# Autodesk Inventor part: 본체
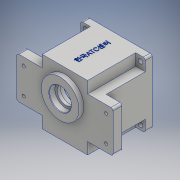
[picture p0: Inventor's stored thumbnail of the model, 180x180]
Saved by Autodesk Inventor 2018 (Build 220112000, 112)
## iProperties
Created: 2020-07
Part Number: 본체
Material: 알루미늄 6061
Document SubType Name: Modeling
Designer: Admin
Density: 2.7 g/cm^3
Appearance: 알루미늄 - 평지
Mass: 876.486 g
Surface Area: 793.573 cm^2
Volume: 324.624 cm^3
Author: Admin
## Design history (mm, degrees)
sketch "스케치1"
  geometry: L1 (47, 47)-(-47, 47); L2 (-47, 47)-(-47, -47); L3 (-47, -47)-(47, -47); L4 (47, -47)-(47, 47); L5 (47, 47)-(-47, -47); L6 (-47, 47)-(47, -47); 1 further point
  constraints: 12 end point, 2 midpoint, 2 parallel, 1 horizontal, 1 perpendicular
  dimensions: "d0" = 94 distance of L1.start L1.end; "d1" = 94 distance of L1.end L2.end
extrude "돌출1" new body sketch "스케치1" stored distance "d2" = 80; taper "d3" = 0 deg
sketch "스케치2"
  geometry: L1 (-65.8, 0)-(65.8, 0) reference; L2 (0, -65.8)-(0, 65.8) reference; L3 (-47, 47)-(-33, 47); L4 (-33, 47)-(-33, 30); L5 (-33, 30)-(-47, 30); L6 (-47, 30)-(-47, 47); L7 (33, 30)-(47, 30); L8 (33, 47)-(33, 30); L9 (47, 47)-(33, 47); L10 (47, 30)-(47, 47); L11 (-33, -30)-(-47, -30); L12 (-33, -47)-(-33, -30); L13 (-47, -47)-(-33, -47); L14 (-47, -30)-(-47, -47); L15 (33, -30)-(47, -30); L16 (33, -47)-(33, -30); L17 (47, -47)-(33, -47); L18 (47, -30)-(47, -47); 2 further points
  constraints: 32 end point, 12 symmetric about line, 2 parallel, 1 coincident, 1 horizontal, 1 perpendicular
  dimensions: "d4" = 33 distance between parallel lines of L2 L4; "d5" = 30 distance between parallel lines of L1 L5
extrude "돌출2" cut sketch "스케치2" distance "d6" = 70; taper "d7" = 0 deg
sketch "스케치3"
  geometry: L1 (-70, 30)-(70, 30); L2 (70, 30)-(70, -30); L3 (70, -30)-(-70, -30); L4 (-70, -30)-(-70, 30); L5 (0, -65.8)-(0, 65.8) reference; L6 (-92.406, 0)-(103.594, 0) reference; 1 further point
  constraints: 8 end point, 2 parallel, 1 horizontal, 1 perpendicular, 2 other
  dimensions: "d8" = 140 distance of L1.start L1.end; "d9" = 60 distance of L1.end L2.end
extrude "돌출3" join sketch "스케치3" distance "d10" = 13; taper "d11" = 0 deg
sketch "스케치4"
  geometry: L1 (-98, 0)-(98, 0) reference; L2 (0, -65.8)-(0, 65.8) reference; C1 r 27.5 at (0, 11); 1 further point
  constraints: 1 centre point, 1 point on line
  dimensions: "d12" = 55 diameter of C1; "d13" = 11 distance from line of L1 C1.centre
extrude "돌출4" join sketch "스케치4" distance "d14" = 7; taper "d15" = 0 deg
sketch "스케치5"
  geometry: C1 r 16 at (0, 0); C2 r 27.5 at (0, 0) reference; 1 further point
  constraints: 1 centre point, 1 concentric
  dimensions: "d16" = 32 diameter of C1
extrude "돌출5" cut sketch "스케치5" distance "d17" = 8.3; taper "d18" = 0 deg
sketch "스케치6"
  geometry: C1 r 12.5 at (0, 0); C2 r 16 at (0, 0) reference; 1 further point
  constraints: 1 centre point, 1 concentric
  dimensions: "d19" = 25 diameter of C1
extrude "돌출6" cut sketch "스케치6" extent not by distance; stored distance "d20" = 8.3; taper "d21" = 0 deg
sketch "스케치7"
  geometry: C1 r 43 at (0, 0); 1 further point
  constraints: 1 centre point, 1 coincident
  dimensions: "d22" = 86 diameter of C1
extrude "돌출7" cut sketch "스케치7" distance "d23" = 9; taper "d24" = 0 deg
sketch "스케치8"
  geometry: C1 r 40 at (0, 0); 1 further point
  constraints: 1 centre point, 1 coincident
  dimensions: "d25" = 80 diameter of C1
extrude "돌출8" cut sketch "스케치8" distance "d26" = 55; taper "d27" = 0 deg
sketch "스케치9"
  geometry: C1 r 17.5 at (0, -11); C2 r 12.5 at (0, -11) reference; 1 further point
  constraints: 1 centre point, 1 concentric
  dimensions: "d28" = 35 diameter of C1
extrude "돌출9" cut sketch "스케치9" distance "d29" = 10; taper "d30" = 0 deg
sketch "스케치10"
  geometry: C1 r 17.5 at (0, -11) reference; C2 r 40 at (0, 0); A1 r 21 centre (0, -11) between (-8.978, 7.984) and (8.978, 7.984); A2 r 15 centre (0, 20) between (8.978, 7.984) and (-8.978, 7.984); 1 further point
  constraints: 4 point on circle, 3 centre point, 1 coincident, 1 concentric, 1 vertical alignment
  dimensions: "d31" = 42 diameter of A1; "d32" = 30 diameter of A2; "d33" = 31 distance of A2.centre A1.centre; "d34" = 80 diameter of C2
extrude "돌출10" cut sketch "스케치10" distance "d35" = 7; taper "d36" = 0 deg
sketch "스케치11"
  geometry: C1 r 11 at (0, 20); A1 r 15 centre (0, 20) between (8.978, 7.984) and (-8.978, 7.984) reference; 1 further point
  constraints: 1 centre point, 1 concentric
  dimensions: "d37" = 22 diameter of C1
extrude "돌출11" cut sketch "스케치11" distance "d38" = 7; taper "d39" = 0 deg
sketch "스케치12"
  geometry: C1 r 9.5 at (0, 0); C2 r 11 at (0, 0) reference; 1 further point
  constraints: 1 centre point, 1 concentric
  dimensions: "d40" = 19 diameter of C1
extrude "돌출12" cut sketch "스케치12" distance "d41" = 3; taper "d42" = 0 deg
sketch "스케치13"
  geometry: L1 (0, -65.8)-(0, 65.8) reference; L2 (-98, 0)-(98, 0) reference; C1 r 3.5 at (-40, 40); C2 r 3.5 at (40, 40); C3 r 3.5 at (-40, -40); C4 r 3.5 at (40, -40); 1 further point
  constraints: 4 centre point, 1 horizontal, 1 vertical, 6 other
  dimensions: "d43" = 7 diameter of C1; "d44" = 40 distance from line of L1 C1.centre; "d45" = 40 distance from line of L2 C1.centre; "d48" = 80 distance of C1.centre C2.centre; "d51" = 80 distance of C1.centre C3.centre
extrude "돌출13" cut sketch "스케치13" extent not by distance; stored distance "d54" = 3; taper "d55" = 0 deg
sketch "스케치14"
  geometry: L1 (0, 65.8)-(0, -65.8) reference; L2 (-98, 0)-(98, 0) reference; C1 r 5 at (60, -19); C2 r 2.25 at (60, -19); C3 r 5 at (-60, -19); C4 r 2.25 at (-60, -19); C5 r 5 at (60, 19); C6 r 2.25 at (60, 19); C7 r 5 at (-60, 19); C8 r 2.25 at (-60, 19); 1 further point
  constraints: 8 centre point, 4 coincident, 1 horizontal, 1 vertical, 12 other
  dimensions: "d56" = 10 diameter of C1; "d57" = 4.5 diameter of C2; "d58" = 19 distance from line of L2 C1.centre; "d59" = 60 distance from line of L1 C1.centre; "d62" = 120 distance of C1.centre C3.centre; "d65" = 38 distance of C1.centre C5.centre
extrude "돌출14" cut sketch "스케치14" extent not by distance; stored distance "d68" = 3; taper "d69" = 0 deg
extrude "돌출15" cut sketch "스케치14" distance "d70" = 5; taper "d71" = 0 deg
sketch "스케치15"
  geometry: L1 (0, 65.8)-(0, -65.8) reference; L2 (-98, 0)-(98, 0) reference; L3 (39.799, -4)-(35.777, -4); L4 (39.799, 4)-(35.777, 4); L5 (-35.777, 4)-(-39.799, 4); L6 (-35.777, -4)-(-39.799, -4); A1 r 36 centre (0, 0) between (-36, 0) and (36, 0); A2 r 4 centre (-36, 0) between (-36, -4) and (-36, 4); A3 r 4 centre (36, 0) between (36, 4) and (36, -4); A4 r 40 centre (0, 0) between (39.799, -4) and (39.799, 4); A5 r 40 centre (0, 0) between (-39.799, 4) and (-39.799, -4); A6 r 40 centre (0, 0) between (39.799, -4) and (39.799, 4) reference; 1 further point
  constraints: 14 point on circle, 8 end point, 6 point on line, 5 centre point, 4 horizontal, 4 tangent, 2 coincident, 2 concentric
  dimensions: "d72" = 72 diameter of A1; "d74" = 8 diameter of A2; "d75" = 8 diameter of A3
extrude "돌출16" join sketch "스케치15" stored distance "d76" = 5; taper "d77" = 0 deg
sketch "스케치16"
  geometry: A1 r 4 centre (36, 0) between (36, 4) and (36, -4) reference; A2 r 4 centre (-36, 0) between (-36, -4) and (-36, 4) reference; 3 further points
  constraints: 2 coincident
hole "구멍1" sketch "스케치16" at (-36, 0), (36, 0) diameter "d78" = 3.242; stored, may be unused: countersink angle "d82" = 90 deg, drill point angle "d84" = 118 deg; dims "d79" = 7, "d80" = 4, "d81" = 2, "d83" = 9
fillet "모깎기1" dims "d85" = 3, "d86" = 3, "d87" = 3
chamfer "모따기1" distance "d88" = 0.8; stored, may be unused: second distance "d89" = 2, angle "d90" = 30 deg
chamfer "모따기2" distance "d91" = 1; stored, may be unused: second distance "d92" = 2, angle "d93" = 30 deg
sketch "스케치17"
  geometry: L1 (-11, 80)-(77, 80) reference; L2 (33, -24.4)-(33, 97.4) reference; 2 further points
  constraints: 1 point on line, 1 other
  dimensions: "d94" = 40 distance from line of L1 point (33, 40)
feature "엠보싱1" sketch "스케치17" dims "d0" = 94, "d1" = 94, "d4" = 33, "d5" = 30, "d95" = 0.5, "d96" = 0
node "솔리드1"
